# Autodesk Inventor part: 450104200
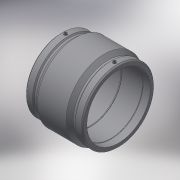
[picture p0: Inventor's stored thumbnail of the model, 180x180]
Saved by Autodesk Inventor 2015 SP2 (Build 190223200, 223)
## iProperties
Created: 2017-06
Part Number: 450104200
Material: Generic
Description: PLASSON COUPLER 200 PN25
Document SubType Name: Modeling
Designer: KIM
Mass: 8622.19 g
Surface Area: 6772.47 cm^2
Volume: 8622.19 cm^3
Density: 1 g/cm^3
Appearance: Default
Author: KIM
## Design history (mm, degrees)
derived "450104.ipt"
feature "Solid1::450104.ipt"
tag "TaggingFeature1"
body "Solid1"
other parameters: "d0" = 223, "d2" = 249, "d4" = 55.75, "d5" = 224.1, "d8" = 168 deg, "d10" = 44, "d11" = 14.66667, "d13" = 223, "d14" = 17.6296, "d17" = 198, "d19" = 3.52592, "d20" = 168 deg, "d22" = 234.06, "d23" = 249, "d24" = 227.0382, "d25" = 135 deg, "d26" = 111.5, "d27" = 135 deg, "d29" = 126, "d30" = 15, "d31" = 78.05, "d34" = 5 deg, "d35" = 15, "d39" = 5 deg, "d41" = 4, "d42" = 14, "d43" = 0, "d45" = 4, "d46" = 14, "d47" = 0, "d48" = 3, "d49" = 0, "d50" = 3, "d51" = 0, "d52" = 31.9, "d53" = 7.975, "L_" = 223, "D_" = 249, "A_" = 126, "d_2" = 12
